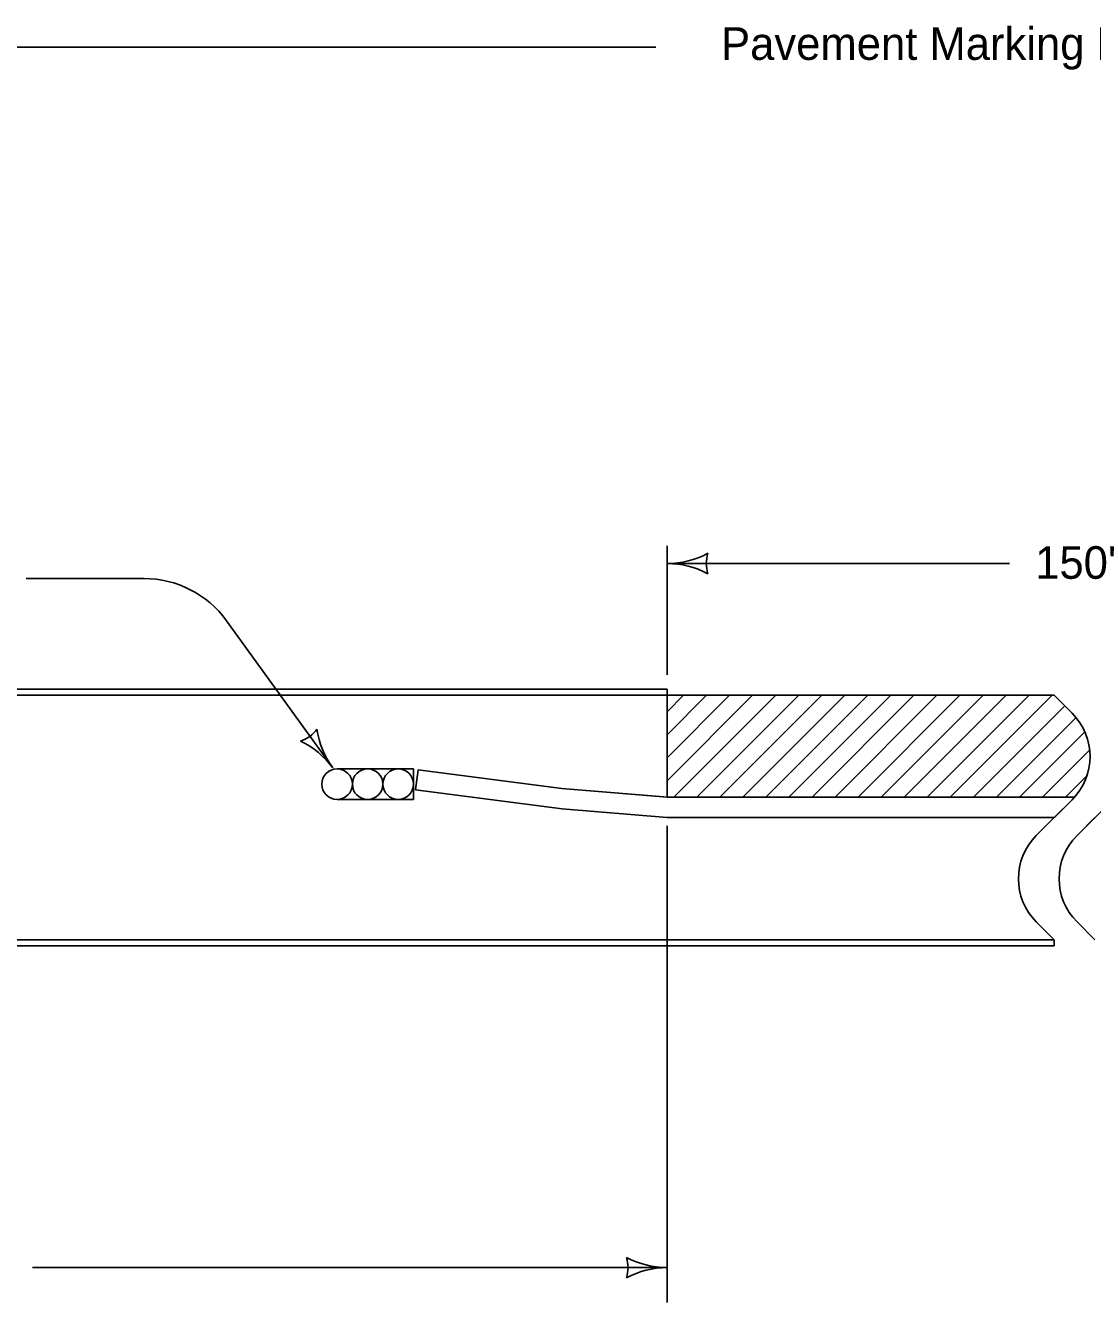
# Model space of a CAD drawing. Extents: x 10124 to 16850, y 7924 to 12166.
# Drawn here: x 14719 to 15243, y 9127 to 9753 of the extents above; entities that cross this region are included whole.
import ezdxf

# ---------------------------------------------------------------- set-up
doc = ezdxf.new("R2010")
doc.units = 0
for name, color, linetype in [('dsnCellElements', 7, 'Continuous'), ('dsnStdLineWork', 7, 'Continuous'), ('Level 2', 7, 'Continuous')]:
    doc.layers.add(name, color=color, linetype=linetype)

msp = doc.modelspace()

# ---------------------------------------------------------------- linework, layer by layer
at = {"layer": 'dsnCellElements'}
for centre, radius, start, end in [((14849.08, 9417.87), 16.42, 288.56567, 324.03237), ((14904.43, 9414.31), 42.5, 188.22653, 216.29902), ((14835.92, 9363.99), 42.5, 36.29902, 64.37151), ((14998.64, 9143.96), 16.42, 342.26665, 17.73335), ((15034.28, 9186.46), 42.5, 241.92751, 270), ((15034.28, 9101.46), 42.5, 90, 118.07249)]:
    msp.add_arc(centre, radius, start, end, dxfattribs=at)
at = {"layer": 'dsnStdLineWork'}
for p, q in [((14842.25, 9427.79), (14369.28, 9427.79)), ((15034.28, 9427.79), (14842.25, 9427.79)), ((14842.25, 9427.79), (14844.42, 9424.79)), ((14844.42, 9424.79), (14842.25, 9427.79)), ((15034.28, 9424.79), (15034.28, 9427.79)), ((15034.28, 9427.79), (15034.28, 9424.79)), ((14369.28, 9424.79), (14844.42, 9424.79)), ((13724.28, 9304.79), (15224.27, 9304.79)), ((13724.28, 9304.79), (15224.27, 9304.79)), ((13724.28, 9301.79), (15224.27, 9301.79)), ((13724.28, 9301.79), (15224.27, 9301.79)), ((15224.27, 9304.79), (14374.28, 9304.79)), ((15224.27, 9301.79), (15224.27, 9304.79)), ((15224.27, 9301.79), (15224.27, 9304.79))]:
    msp.add_line(p, q, dxfattribs=at)
for points in [[(13724.28, 9427.79), (15034.28, 9427.79)], [(13723.86, 9424.79), (15033.86, 9424.79)], [(13724.28, 9424.79), (15034.28, 9424.79)], [(14844.42, 9424.79), (15033.86, 9424.79), (15034.28, 9424.79)]]:
    msp.add_lwpolyline(points, dxfattribs=at)
at = {"layer": 'Level 2'}
for p, q in [((14369.28, 9742.96), (15028.7, 9742.96)), ((15034.28, 9434.79), (15034.28, 9498.09)), ((15034.28, 9489.48), (15202.35, 9489.48)), ((14777.43, 9482.11), (14719.64, 9482.11)), ((14870.17, 9389.15), (14817.95, 9461.4)), ((15034.28, 9424.79), (13724.28, 9424.79)), ((15034.28, 9416.71), (15042.35, 9424.79)), ((15034.28, 9405.41), (15053.65, 9424.79)), ((15034.28, 9394.11), (15064.95, 9424.79)), ((15034.28, 9374.79), (15034.28, 9424.79)), ((15034.28, 9382.81), (15076.25, 9424.79)), ((15034.28, 9374.79), (15034.28, 9424.79)), ((15037.55, 9374.79), (15087.55, 9424.79)), ((15048.85, 9374.79), (15098.85, 9424.79)), ((15060.15, 9374.79), (15110.15, 9424.79)), ((15071.46, 9374.79), (15121.46, 9424.79)), ((15082.78, 9374.79), (15132.78, 9424.79)), ((15094.09, 9374.79), (15144.09, 9424.79)), ((15155.4, 9424.79), (15105.4, 9374.79)), ((15116.72, 9374.79), (15166.71, 9424.79)), ((15128.03, 9374.79), (15178.03, 9424.79)), ((15139.34, 9374.79), (15189.34, 9424.79)), ((15150.66, 9374.79), (15200.66, 9424.79)), ((15161.97, 9374.79), (15211.97, 9424.79)), ((15173.28, 9374.79), (15223.28, 9424.79)), ((15184.6, 9374.79), (15229.44, 9419.62)), ((15233.06, 9416), (15224.27, 9424.79)), ((15195.91, 9374.79), (15235, 9413.87)), ((15207.22, 9374.79), (15239.31, 9406.87)), ((15218.54, 9374.79), (15241.68, 9397.93)), ((14872.24, 9388.69), (14909.76, 9388.69)), ((14872.24, 9388.69), (14909.76, 9388.69)), ((14909.76, 9388.69), (14909.76, 9373.69)), ((14909.76, 9388.69), (14909.76, 9373.69)), ((14912.03, 9388.29), (14910.77, 9378.42)), ((14912.03, 9388.29), (14910.77, 9378.42)), ((14910.77, 9378.42), (14912.03, 9388.29)), ((14910.77, 9378.42), (14912.03, 9388.29)), ((14982.55, 9379.11), (14912.03, 9388.29)), ((14982.55, 9379.11), (14912.03, 9388.29)), ((14982.55, 9379.11), (14912.03, 9388.29)), ((14912.03, 9388.29), (14982.55, 9379.11)), ((15229.85, 9374.79), (15240.28, 9385.21)), ((14910.77, 9378.45), (14982.71, 9369.11)), ((14910.77, 9378.42), (14982.71, 9369.11)), ((14982.71, 9369.11), (14910.77, 9378.42)), ((14982.71, 9369.11), (14910.77, 9378.42)), ((15034.62, 9374.78), (14982.55, 9379.11)), ((15034.28, 9374.81), (14982.55, 9379.11)), ((15034.28, 9374.79), (14982.55, 9379.11)), ((14982.55, 9379.11), (15034.28, 9374.79)), ((15034.28, 9374.79), (15034.28, 9374.81)), ((15034.55, 9374.79), (15034.28, 9374.79)), ((15234.21, 9374.79), (15034.28, 9374.79)), ((15034.62, 9374.78), (15034.55, 9374.79)), ((15234.21, 9374.79), (15034.62, 9374.79)), ((14909.76, 9373.69), (14872.24, 9373.69)), ((14909.76, 9373.69), (14872.24, 9373.69)), ((14982.71, 9369.11), (15034.28, 9364.79)), ((14982.71, 9369.11), (15034.28, 9364.79)), ((15034.28, 9364.79), (14982.71, 9369.11)), ((15034.28, 9364.79), (14982.71, 9369.11)), ((15215.49, 9356), (15233.06, 9373.57)), ((15224.27, 9364.79), (15233.06, 9373.57)), ((15235.49, 9356), (15253.06, 9373.57)), ((15224.27, 9364.79), (15034.27, 9364.79)), ((15034.28, 9364.79), (15224.27, 9364.79)), ((15034.28, 9364.79), (15224.27, 9364.79)), ((15224.27, 9364.79), (15034.28, 9364.79)), ((15215.49, 9356), (15224.27, 9364.79)), ((15034.28, 9126.84), (15034.28, 9360.69)), ((15224.27, 9304.79), (15215.49, 9313.57)), ((15224.27, 9304.79), (15215.49, 9313.57)), ((15244.27, 9304.79), (15235.49, 9313.57)), ((15235.49, 9313.57), (15244.27, 9304.79)), ((13724.28, 9304.79), (15224.27, 9304.79)), ((14722.76, 9143.96), (15034.28, 9143.96)), ((14757.35, 9143.96), (14806.96, 9143.96))]:
    msp.add_line(p, q, dxfattribs=at)
for points in [[(15034.28, 9424.79), (15224.27, 9424.79)], [(14872.24, 9388.69), (14872.24, 9388.69)], [(15034.62, 9374.79), (15034.62, 9374.78)], [(14872.24, 9373.69), (14872.24, 9373.69)], [(15224.27, 9364.79), (15224.27, 9364.79)], [(15224.27, 9364.79), (15224.27, 9364.79)], [(15244.27, 9364.79), (15244.27, 9364.79), (15235.49, 9356)]]:
    msp.add_lwpolyline(points, dxfattribs=at)
for centre in [(14872.24, 9381.19), (14872.24, 9381.19), (14887.25, 9381.19), (14887.25, 9381.19), (14902.25, 9381.19), (14902.25, 9381.19)]:
    msp.add_circle(centre, 7.5, dxfattribs=at)
for centre, radius, start, end in [((15034.28, 9531.98), 42.5, 270, 298.07249), ((15069.91, 9489.48), 16.42, 162.26665, 197.73335), ((15034.28, 9446.98), 42.5, 61.92751, 90), ((14777.43, 9432.11), 50, 35.86205, 90), ((15211.85, 9394.79), 30, 315, 45), ((14872.24, 9381.19), 7.5, 90.00277, 269.99723), ((15211.85, 9394.79), 30, 315, 318.1884), ((15236.7, 9334.79), 30, 135, 225), ((15236.7, 9334.79), 30, 135, 225), ((15256.7, 9334.79), 30, 135, 225), ((15256.7, 9334.79), 30, 135, 225)]:
    msp.add_arc(centre, radius, start, end, dxfattribs=at)

# ---------------------------------------------------------------- texts
for s, p in [('Pavement Marking Removal Limits', (15060.75, 9736.64)), ("150'", (15214.94, 9481.98))]:
    msp.add_text(s, height=16, dxfattribs=at).set_placement(p)

doc.saveas('drawing.dxf')
